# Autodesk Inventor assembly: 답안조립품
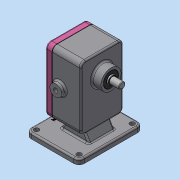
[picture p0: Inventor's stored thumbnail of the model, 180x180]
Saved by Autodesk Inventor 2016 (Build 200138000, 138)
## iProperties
Created: 2020-04
Part Number: 답안조립품
Material: 일반
Document SubType Name: Assembly
Designer: Administrator
Author: Administrator
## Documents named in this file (11)
- C:\Users\Administrator\Desktop\700407V1005\답안조립품.iam
- C:\Users\Administrator\Desktop\700407V1005\본체.ipt
- C:\Users\Administrator\Desktop\700407V1005\오일 실 16 28 7.ipt
- C:\Users\Administrator\Desktop\700407V1005\베어링부시.ipt
- C:\Users\Administrator\Desktop\700407V1005\메인축.ipt
- C:\Users\Administrator\Desktop\700407V1005\서브축.ipt
- C:\Users\Administrator\Desktop\700407V1005\키 6 x 6 x 18.ipt
- C:\Users\Administrator\Desktop\700407V1005\스퍼기어.ipt
- C:\Users\Administrator\Desktop\700407V1005\개스킷.ipt
- C:\Users\Administrator\Desktop\700407V1005\커버.ipt
- C:\Users\Administrator\Desktop\700407V1005\볼트 M5.ipt
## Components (1 placed, 1 different names)
1. 개스킷:1
## Component patterns: 구성요소 패턴 1:2 (2 elements), 구성요소 패턴 3:2 (2 elements)
